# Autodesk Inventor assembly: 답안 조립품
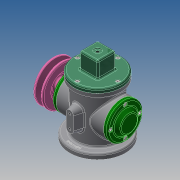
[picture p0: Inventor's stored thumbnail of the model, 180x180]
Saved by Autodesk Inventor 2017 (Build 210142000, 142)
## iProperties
Part Number: 답안 조립품
Material: 일반
Document SubType Name: Assembly
Designer: MRC
Author: MRC
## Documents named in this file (18)
- C:\Users\MRC\Desktop\730206V1001\답안 조립품.iam
- C:\Users\MRC\Desktop\730206V1001\본체.ipt
- C:\Users\MRC\Desktop\730206V1001\덮개.ipt
- C:\Users\MRC\Desktop\730206V1001\앞커버.ipt
- C:\Users\MRC\Desktop\730206V1001\뒤커버.ipt
- C:\Users\MRC\Desktop\730206V1001\편심축.ipt
- C:\Users\MRC\Desktop\730206V1001\베어링 17 x 40 x 12.ipt
- C:\Users\MRC\Desktop\730206V1001\링크.ipt
- C:\Users\MRC\Desktop\730206V1001\슬라이더.ipt
- C:\Users\MRC\Desktop\730206V1001\클레비스 핀 6 x 22.ipt
- 클레비스 핀 6 x 22.ipt
- C:\Users\MRC\Desktop\730206V1001\E-링.ipt
- C:\Users\MRC\Desktop\730206V1001\오일 실 17 30 8.ipt
- C:\Users\MRC\Desktop\730206V1001\키 4 x 4 x 12.ipt
- C:\Users\MRC\Desktop\730206V1001\V-벨트풀리.ipt
- C:\Users\MRC\Desktop\730206V1001\와셔 4x16.ipt
- C:\Users\MRC\Desktop\730206V1001\볼트 M4 x 10.ipt
- C:\Users\MRC\Desktop\730206V1001\볼트 M4 x 8.ipt
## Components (2 placed, 2 different names)
1. E-링:1
2. V-벨트풀리:1
